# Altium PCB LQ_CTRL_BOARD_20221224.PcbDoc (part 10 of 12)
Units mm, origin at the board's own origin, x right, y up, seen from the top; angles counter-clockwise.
Board outline 260 x 142 mm, 6 copper layers (Top Layer, Mid-Layer 1, Mid-Layer 2, Mid-Layer 3, Mid-Layer 4, Bottom Layer); 1105 components, 1039 nets, 3898 pads, 1277 vias.
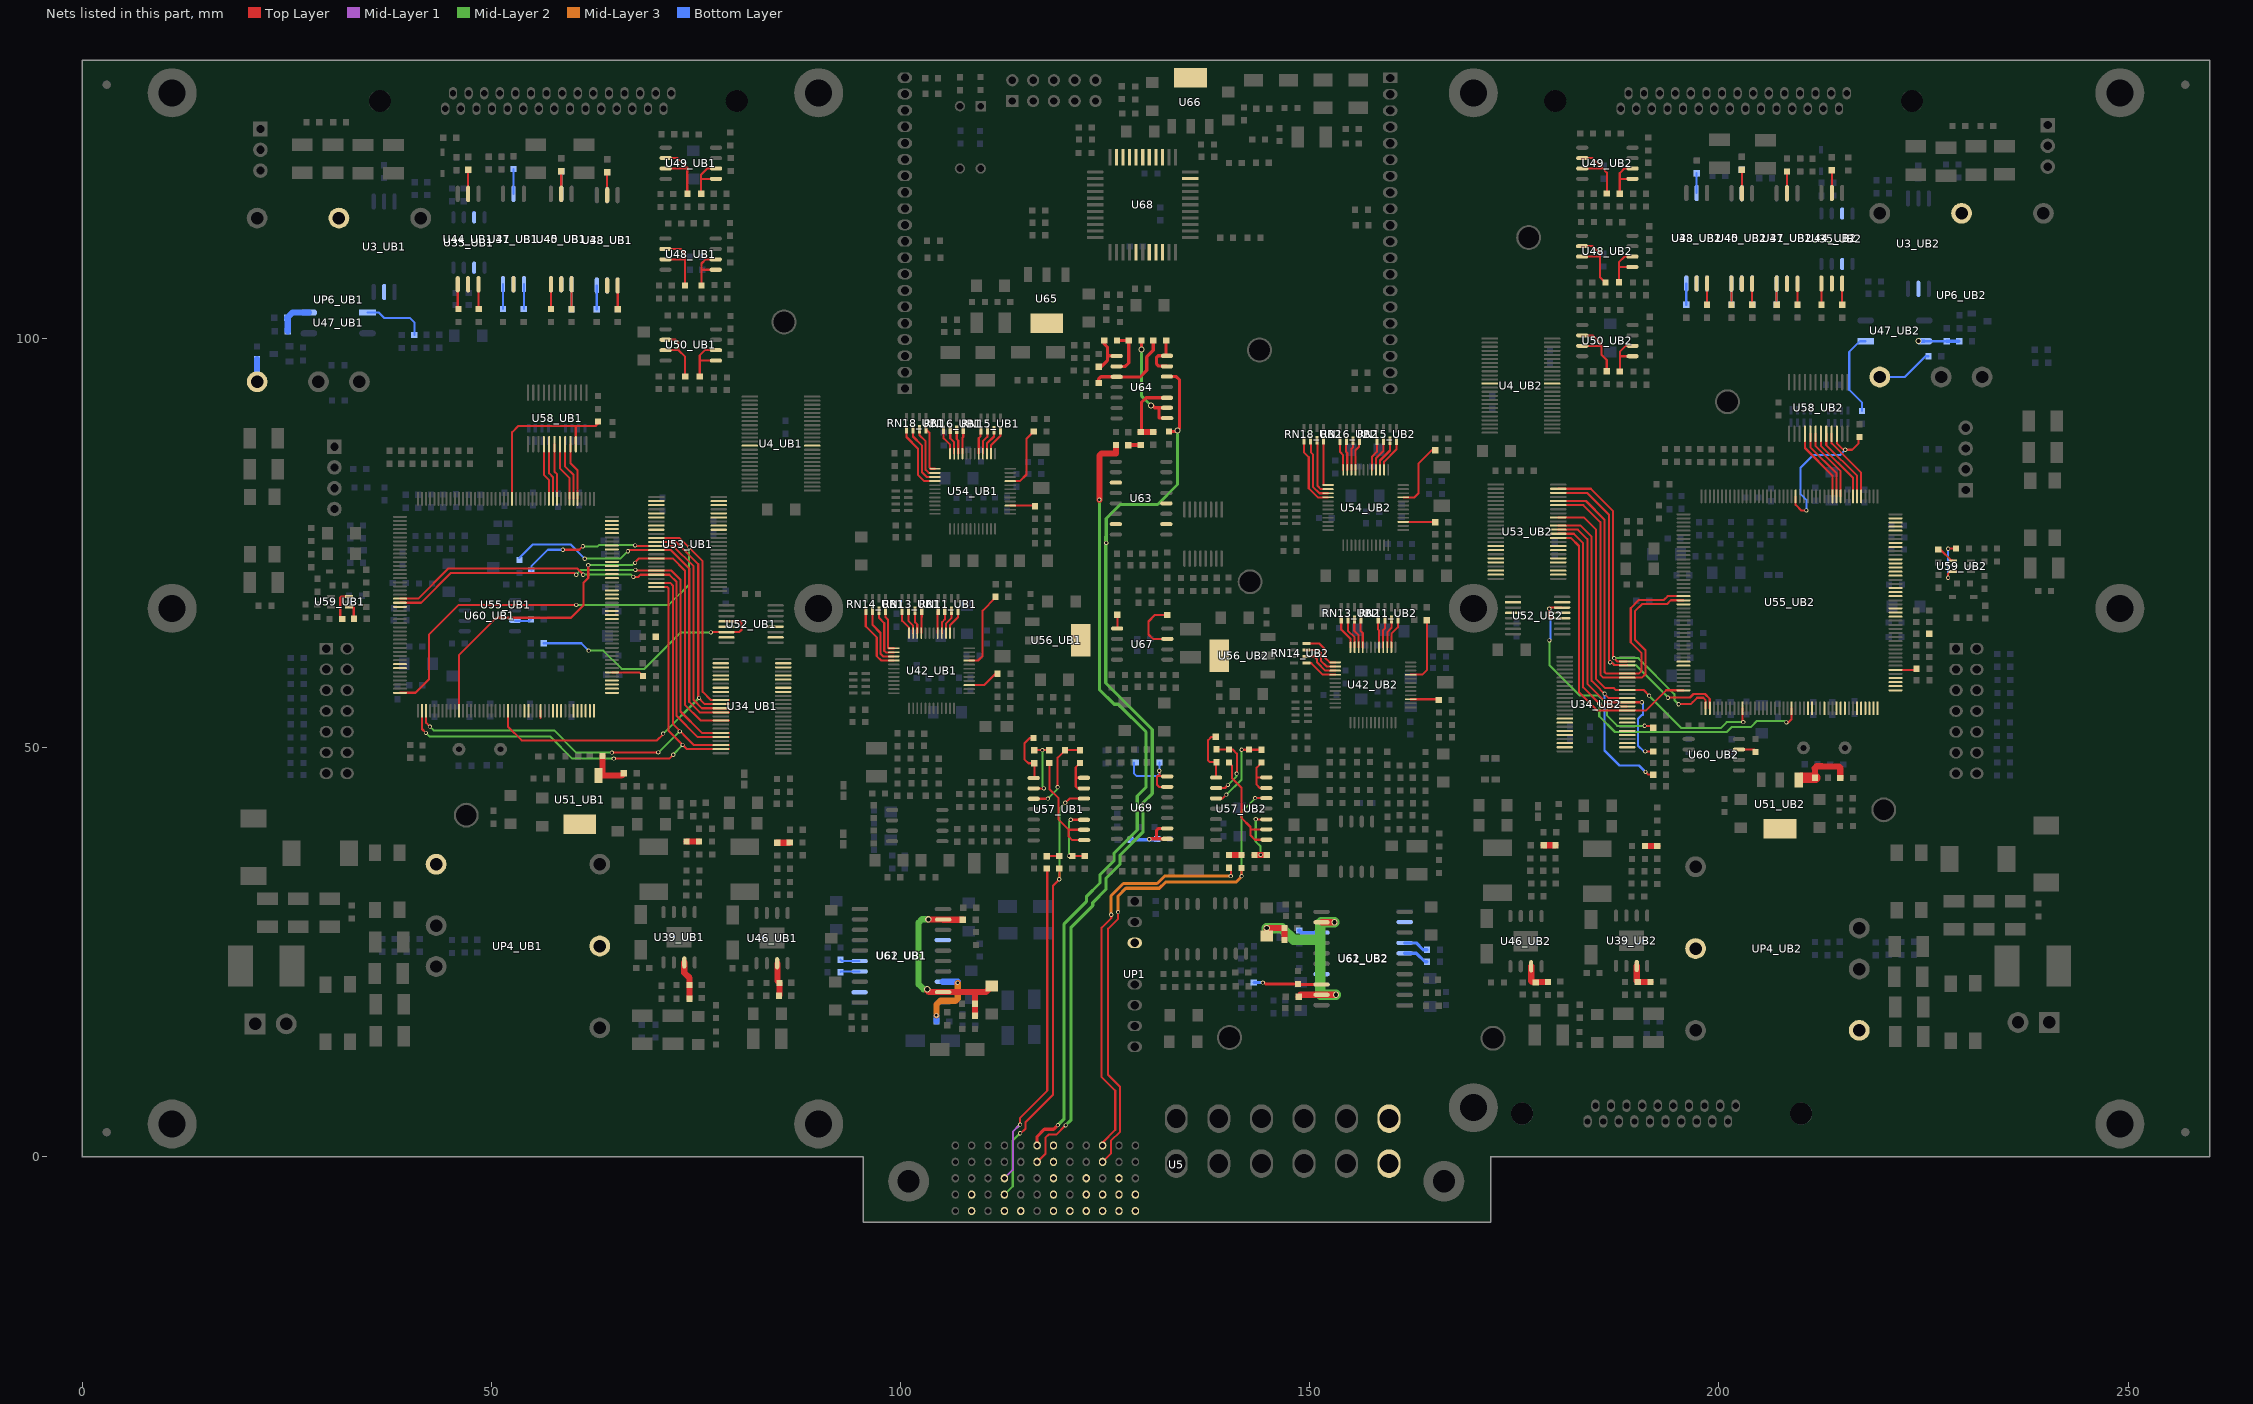
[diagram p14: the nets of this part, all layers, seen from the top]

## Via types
v1: diameter 0.508, hole 0.305, Top Layer to Bottom Layer, 845 vias
v2: diameter 0.762, hole 0.508, Top Layer to Bottom Layer, 317 vias
v3: diameter 1.27, hole 0.762, Top Layer to Bottom Layer, 77 vias
v4: diameter 2.032, hole 1.524, Top Layer to Bottom Layer, 15 vias
v5: diameter 2.032, hole 1.27, Top Layer to Bottom Layer, 11 vias
v6: diameter 1.27, hole 0.711, Top Layer to Bottom Layer, 8 vias
v7: diameter 2.54, hole 1.778, Top Layer to Bottom Layer, 3 vias
v8: diameter 1.524, hole 1.016, Top Layer to Bottom Layer, 1 vias

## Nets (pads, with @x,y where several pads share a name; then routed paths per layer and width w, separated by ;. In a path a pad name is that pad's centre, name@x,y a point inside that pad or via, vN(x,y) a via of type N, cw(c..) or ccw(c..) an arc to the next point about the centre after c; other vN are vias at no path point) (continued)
NetR226_UB2_2: R226_UB2.2 U37_UB2.3 | length 2.6
  Bottom Layer w0.254: U37_UB2.3@207.06,106.68 U37_UB2.3@207.06,106.68 R226_UB2.2@207.061,104.115
NetR227_UB1_2: R227_UB1.2 U38_UB1.3 | length 2.9
  Bottom Layer w0.254: R227_UB1.2@62.89,103.556 U38_UB1.3@62.89,106.451
NetR227_UB2_2: R227_UB2.2 U38_UB2.3 | length 2.6
  Top Layer w0.254: R227_UB2.2@198.552,104.089 198.552,106.7 U38_UB2.3@198.557,106.705
NetR232_UB1_2: R232_UB1.2 U40_UB1.1 | length 3
  Top Layer w0.254: R232_UB1.2@57.282,103.581 U40_UB1.1@57.282,106.604
NetR232_UB2_2: R232_UB2.2 U40_UB2.1 | length 2.6
  Bottom Layer w0.254: R232_UB2.2@204.069,104.089 U40_UB2.1@204.069,106.68
NetR233_UB1_2: R233_UB1.2 U41_UB1.1 | length 3
  Bottom Layer w0.254: R233_UB1.2@53.98,103.581 U41_UB1.1@53.98,106.604
NetR233_UB2_2: R233_UB2.2 U41_UB2.1 | length 2.6
  Top Layer w0.254: U41_UB2.1@207.06,106.68 U41_UB2.1@207.06,106.68 R233_UB2.2@207.061,104.115
NetR235_UB1_1: R235_UB1.1 U41_UB1.5 | length 3
  Bottom Layer w0.254: U41_UB1.5@52.71,117.653 R235_UB1.1@52.71,120.675
NetR235_UB2_1: R235_UB2.1 U41_UB2.5 | length 2.7
  Top Layer w0.254: U41_UB2.5@208.33,117.729 R235_UB2.1@208.33,120.396
NetR236_UB1_2: R236_UB1.2 R243_UB1.1 U39_UB1.3 | length 4.7
  Top Layer w0.762: U39_UB1.3@73.584,23.749 73.584,22.479 74.219,21.844 R236_UB1.2@74.219,20.98 R243_UB1.1@74.219,19.304
NetR236_UB2_2: R236_UB2.2 R243_UB2.1 U39_UB2.3 | length 3.6
  Top Layer w0.762: U39_UB2.3@189.967,23.317 189.967,21.488 R236_UB2.2@190.094,21.361 R243_UB2.1@191.643,21.361
NetR237_UB1_1: R237_UB1.1 U40_UB1.5 | length 2.8
  Top Layer w0.254: U40_UB1.5@58.552,117.653 R237_UB1.1@58.552,120.421
NetR237_UB2_1: R237_UB2.1 U40_UB2.5 | length 2.9
  Bottom Layer w0.254: U40_UB2.5@202.799,117.729 R237_UB2.1@202.799,120.599
NetR238_UB1_2: R238_UB1.2 R239_UB1.1 | length 1.5
  Top Layer w0.762: R239_UB1.1@73.863,38.532 R238_UB1.2@75.387,38.532
NetR238_UB2_2: R238_UB2.2 R239_UB2.1 | length 1.5
  Top Layer w0.762: R239_UB2.1@190.957,37.973 R238_UB2.2@192.456,37.973
NetR240_UB1_2: R240_UB1.2 U40_UB1.3 | length 3.1
  Top Layer w0.254: R240_UB1.2@59.817,103.556 59.817,106.598 U40_UB1.3@59.822,106.604
NetR240_UB2_2: R240_UB2.2 U40_UB2.3 | length 2.6
  Bottom Layer w0.254: R240_UB2.2@201.529,104.089 U40_UB2.3@201.529,106.68
NetR241_UB1_2: R241_UB1.2 U41_UB1.3 | length 3
  Bottom Layer w0.254: R241_UB1.2@51.44,103.581 U41_UB1.3@51.44,106.604
NetR241_UB2_2: R241_UB2.2 U41_UB2.3 | length 2.6
  Top Layer w0.254: U41_UB2.3@209.6,106.68 U41_UB2.3@209.6,106.68 R241_UB2.2@209.601,104.115
NetR244_UB1_2: R244_UB1.2 U42_UB1.3 | length 4
  Top Layer w0.254: U42_UB1.3@108.399,57.635 110.238,57.635 111.608,59.004 R244_UB1.2@111.862,59.004
NetR244_UB2_2: R244_UB2.2 U42_UB2.3 | length 3.5
  Top Layer w0.254: U42_UB2.3@162.334,55.9 R244_UB2.2@165.61,55.9 ; R244_UB2.2@165.61,55.646 R244_UB2.2@165.76,55.796
NetR246_UB1_2: R246_UB1.2 U44_UB1.1 | length 3.1
  Top Layer w0.254: U44_UB1.1@45.904,106.604 45.904,103.656 R246_UB1.2@45.979,103.581
NetR246_UB2_2: R246_UB2.2 U44_UB2.1 | length 2.6
  Top Layer w0.254: R246_UB2.2@212.527,104.089 U44_UB2.1@212.527,106.705
NetR247_UB1_2: R247_UB1.2 U43_UB1.3 | length 2.9
  Top Layer w0.254: U43_UB1.3@65.436,106.451 65.456,106.431 R247_UB1.2@65.456,103.556
NetR247_UB2_2: R247_UB2.2 U43_UB2.3 | length 2.6
  Bottom Layer w0.254: R247_UB2.2@196.012,104.089 196.012,106.7 U43_UB2.3@196.017,106.705
NetR248_UB1_1: R248_UB1.1 U43_UB1.5 | length 2.8
  Top Layer w0.254: U43_UB1.5@64.166,117.5 R248_UB1.1@64.166,120.294
NetR248_UB2_1: R248_UB2.1 U43_UB2.5 | length 2.4
  Bottom Layer w0.254: U43_UB2.5@197.287,117.754 R248_UB2.1@197.287,120.167
NetR249_UB1_2: R249_UB1.2 U45_UB1.1 | length 3.1
  Bottom Layer w0.254: R249_UB1.2@59.817,103.556 59.822,103.561 U45_UB1.1@59.822,106.604
NetR249_UB2_2: R249_UB2.2 U45_UB2.1 | length 2.6
  Top Layer w0.254: R249_UB2.2@201.529,104.089 U45_UB2.1@201.529,106.68
NetR250_UB1_2: R250_UB1.2 UP6_UB1.6 | length 2.7
  Bottom Layer w0.762: R250_UB1.2@21.387,97.434 21.387,94.697 UP6_UB1.6@21.392,94.691
NetR250_UB2_2: R250_UB2.2 UP6_UB2.6 | length 7
  Bottom Layer w0.254: UP6_UB2.6@219.665,95.275 222.707,95.275 225.247,97.815 R250_UB2.2@225.603,97.815
NetR251_UB1_1: R251_UB1.1 U45_UB1.5 | length 2.8
  Bottom Layer w0.254: U45_UB1.5@58.552,117.653 R251_UB1.1@58.552,120.421
NetR251_UB2_1: R251_UB2.1 U45_UB2.5 | length 2.9
  Top Layer w0.254: U45_UB2.5@202.799,117.729 R251_UB2.1@202.799,120.599
NetR252_UB1_1: R252_UB1.1 U44_UB1.5 | length 2.9
  Top Layer w0.254: U44_UB1.5@47.174,117.653 R252_UB1.1@47.174,120.599
NetR252_UB2_1: R252_UB2.1 U44_UB2.5 | length 2.8
  Top Layer w0.254: U44_UB2.5@213.797,117.754 R252_UB2.1@213.797,120.548
NetR253_UB1_2: R253_UB1.2 U44_UB1.3 | length 3
  Top Layer w0.254: U44_UB1.3@48.444,106.604 48.444,103.6 R253_UB1.2@48.463,103.581
NetR253_UB2_2: R253_UB2.2 U44_UB2.3 | length 2.6
  Top Layer w0.254: R253_UB2.2@215.067,104.089 U44_UB2.3@215.067,106.705
NetR254_UB1_2: R254_UB1.2 U45_UB1.3 | length 3
  Bottom Layer w0.254: R254_UB1.2@57.282,103.581 U45_UB1.3@57.282,106.604
NetR254_UB2_2: R254_UB2.2 U45_UB2.3 | length 2.6
  Top Layer w0.254: R254_UB2.2@204.069,104.089 U45_UB2.3@204.069,106.68
NetR255_UB1_2: R255_UB1.2 U42_UB1.9 | length 9.8
  Top Layer w0.254: U42_UB1.9@108.399,60.635 109.479,60.635 110.033,61.189 110.033,66.726 111.597,68.29 R255_UB1.2@111.597,68.428
NetR255_UB2_2: R255_UB2.2 U42_UB2.9 | length 8.3
  Top Layer w0.254: U42_UB2.9@162.334,58.9 163.751,58.9 164.313,59.461 R255_UB2.2@164.313,65.557
NetR256_UB1_1: R256_UB1.1 R260_UB1.2 U47_UB1.6 | length 4.6
  Bottom Layer w0.762: R260_UB1.2@25.121,100.863 25.121,102.464 R256_UB1.1@25.07,102.514 25.705,103.149 U47_UB1.6@27.717,103.149
NetR256_UB2_1: R256_UB2.1 R260_UB2.2 U47_UB2.6 | length 4.8
  Bottom Layer w0.254: U47_UB2.6@225.095,99.644 R260_UB2.2@227.635,99.644
  Bottom Layer w0.381: v2(224.384,99.67) 224.409,99.644 U47_UB2.6@225.095,99.644 ; R260_UB2.2@227.838,99.644 R256_UB2.1@229.362,99.644
NetR257_UB1_1: R257_UB1.1 U47_UB1.1 | length 7.8
  Bottom Layer w0.254: U47_UB1.1@34.88,103.149 36.271,103.149 36.957,102.464 40.081,102.464 40.595,101.95 R257_UB1.1@40.595,100.406
NetR257_UB2_1: R257_UB2.1 U47_UB2.1 | length 10.4
  Bottom Layer w0.254: R257_UB2.1@217.5,91.135 217.5,92.126 215.925,93.701 215.925,98.349 217.221,99.644 U47_UB2.1@217.932,99.644
NetR263_UB1_2: R263_UB1.2 R274_UB1.1 U46_UB1.3 | length 4.1
  Top Layer w0.762: U46_UB1.3@84.988,23.597 84.988,21.463 R263_UB1.2@85.217,21.234 85.217,19.71 R274_UB1.1@85.166,19.66
NetR263_UB2_2: R263_UB2.2 R274_UB2.1 U46_UB2.3 | length 3.9
  Top Layer w0.762: U46_UB2.3@177.063,23.266 177.063,21.488 177.216,21.336 R274_UB2.1@179.121,21.336
NetR265_UB1_1: R265_UB1.1 U48_UB1.6 U48_UB1.7 | length 8.9
  Top Layer w0.254: U48_UB1.7@71.278,109.652 73.665,109.652 ; U48_UB1.6@71.278,110.922 73.127,110.922 73.665,110.383 73.665,109.652 ; R265_UB1.1@73.665,106.451 73.665,109.652
NetR265_UB2_1: R265_UB2.1 U48_UB2.6 U48_UB2.7 | length 8.6
  Top Layer w0.254: U48_UB2.7@183.286,109.987 185.465,109.987 185.471,109.982 ; U48_UB2.6@183.286,111.257 184.551,111.257 185.471,110.338 185.471,109.982 ; R265_UB2.1@186.131,106.807 185.471,107.467 185.471,109.982
NetR266_UB1_1: R266_UB1.1 U49_UB1.1 U49_UB1.2 | length 6.2
  Top Layer w0.254: R266_UB1.1@75.621,117.805 75.621,119.482 ; U49_UB1.1@77.462,119.482 75.621,119.482 ; U49_UB1.2@77.462,120.752 76.403,120.752 75.621,119.97 75.621,119.482
NetR266_UB2_1: R266_UB2.1 U49_UB2.1 U49_UB2.2 | length 5.9
  Top Layer w0.254: R266_UB2.1@187.884,117.678 187.884,120.177 188.458,120.752 U49_UB2.2@189.459,120.752 ; 187.909,119.405 187.985,119.482 U49_UB2.1@189.459,119.482
NetR267_UB1_1: R267_UB1.1 U50_UB1.6 U50_UB1.7 | length 7.8
  Top Layer w0.254: U50_UB1.7@71.303,98.552 72.873,98.552 ; U50_UB1.6@71.303,99.822 72.517,99.822 72.873,99.466 72.873,98.552 ; R267_UB1.1@73.691,95.326 73.691,97.734 72.873,98.552
NetR267_UB2_1: R267_UB2.1 U50_UB2.6 U50_UB2.7 | length 8.6
  Top Layer w0.254: U50_UB2.7@183.312,99.085 185.598,99.085 ; U50_UB2.6@183.312,100.355 184.582,100.355 185.661,99.276 185.661,97.98 186.296,97.346 R267_UB2.1@186.296,95.987
NetR268_UB1_2: R268_UB1.2 R269_UB1.1 | length 1.5
  Top Layer w0.762: R269_UB1.1@84.938,38.379 86.436,38.379 R268_UB1.2@86.462,38.405
NetR268_UB2_2: R268_UB2.2 R269_UB2.1 | length 1.4
  Top Layer w0.762: R269_UB2.1@178.587,38.049 R268_UB2.2@180.035,38.049
NetR282_UB1_1: R282_UB1.1 U48_UB1.1 U48_UB1.2 | length 6.4
  Top Layer w0.254: R282_UB1.1@75.692,106.451 75.692,108.473 ; U48_UB1.1@77.425,108.382 75.783,108.382 75.692,108.473 ; U48_UB1.2@77.425,109.652 76.2,109.652 75.692,109.144 75.692,108.473
NetR282_UB2_1: R282_UB2.1 U48_UB2.1 U48_UB2.2 | length 6
  Top Layer w0.254: R282_UB2.1@187.782,106.858 187.782,108.737 ; U48_UB2.1@189.433,108.717 187.802,108.717 187.782,108.737 ; U48_UB2.2@189.433,109.987 188.464,109.987 187.782,109.306 187.782,108.737
NetR285_UB1_1: R285_UB1.1 U49_UB1.6 U49_UB1.7 | length 8.8
  Top Layer w0.254: U49_UB1.7@71.315,120.752 73.869,120.752 73.945,120.675 ; U49_UB1.6@71.315,122.022 72.771,122.022 73.945,120.848 73.945,120.675 ; R285_UB1.1@73.945,117.805 73.945,120.675
NetR285_UB2_1: R285_UB2.1 U49_UB2.6 U49_UB2.7 | length 8.8
  Top Layer w0.254: U49_UB2.7@183.312,120.752 185.776,120.752 185.788,120.764 ; U49_UB2.6@183.312,122.022 184.531,122.022 185.788,120.764 ; R285_UB2.1@186.309,117.704 186.309,120.244 185.788,120.764
NetR286_UB1_1: R286_UB1.1 U50_UB1.1 U50_UB1.2 | length 6.9
  Top Layer w0.254: R286_UB1.1@75.469,95.326 75.469,97.13 ; U50_UB1.1@77.45,97.282 75.621,97.282 75.469,97.13 ; U50_UB1.2@77.45,98.552 76.104,98.552 75.469,97.917 75.469,97.13
NetR286_UB2_1: R286_UB2.1 U50_UB2.1 U50_UB2.2 | length 5.9
  Top Layer w0.254: R286_UB2.1@187.896,95.936 187.896,97.815 ; U50_UB2.1@189.459,97.815 187.896,97.815 ; U50_UB2.2@189.459,99.085 188.62,99.085 187.896,98.361 187.896,97.815
NetR294_UB1_2: R294_UB1.2 R295_UB1.1 U51_UB1.1 | length 5.8
  Top Layer w0.762: R295_UB1.1@63.602,48.971 63.602,47.092 U51_UB1.1@63.094,46.584 65.913,46.584 R294_UB1.2@66.192,46.863
NetR294_UB2_2: R294_UB2.2 R295_UB2.1 U51_UB2.1 | length 7.5
  Top Layer w0.762: R295_UB2.1@211.76,46.304 211.76,47.422 211.709,47.473 211.938,47.701 212.573,47.701 212.598,47.676 214.681,47.676 214.833,47.523 R294_UB2.2@214.833,46.279
  Top Layer w1.27: U51_UB2.1@210.033,46.304 R295_UB2.1@211.76,46.304
NetR308_UB1_2: R308_UB1.2 U54_UB1.3 | length 3.1
  Top Layer w0.254: U54_UB1.3@113.413,79.56 116.35,79.56 R308_UB1.2@116.434,79.477
NetR308_UB2_2: R308_UB2.2 U54_UB2.3 | length 3.9
  Top Layer w0.254: U54_UB2.3@161.442,77.573 165.301,77.573 R308_UB2.2@165.354,77.52
NetR310_UB1_2: R310_UB1.2 U54_UB1.9 | length 7.9
  Top Layer w0.254: U54_UB1.9@113.413,82.56 114.59,82.56 115.392,83.363 115.392,87.732 R310_UB1.2@116.281,88.621
NetR310_UB2_2: R310_UB2.2 U54_UB2.9 | length 8.4
  Top Layer w0.254: U54_UB2.9@161.442,80.573 162.805,80.573 163.271,81.039 163.271,84.684 164.924,86.336 R310_UB2.2@165.343,86.336
NetR332_UB1_1: R332_UB1.1 R338_UB1.1 U57_UB1.1 | length 6.6
  Top Layer w0.254: R338_UB1.1@116.25,51.181 115.824,51.181 115.138,50.495 115.138,48.59 115.646,48.082 R332_UB1.1@116.357,48.082 116.357,46.36 U57_UB1.1@116.276,46.279
NetR332_UB1_2: R332_UB1.2 R333_UB1.1 U57_UB1.2 | length 7.8
  Top Layer w0.254: U57_UB1.2@116.276,45.009 v1(117.526,45.009) ; R332_UB1.2@116.357,49.657 116.383,49.682 v1(117.348,49.682) R333_UB1.1@118.186,49.682
  Mid-Layer 2 w0.254: v1(117.348,49.682) 117.348,45.187 v1(117.526,45.009)
NetR332_UB2_1: R332_UB2.1 R338_UB2.1 U57_UB2.1 | length 6.6
  Top Layer w0.254: R338_UB2.1@138.532,51.308 137.998,51.308 137.592,50.902 137.592,48.412 137.795,48.209 R332_UB2.1@138.608,48.209 138.557,48.158 U57_UB2.1@138.557,46.33
NetR332_UB2_2: R332_UB2.2 R333_UB2.1 U57_UB2.2 | length 8.6
  Top Layer w0.254: U57_UB2.2@138.557,45.06 139.649,45.06 140.005,45.415 v1(140.005,45.441) ; R332_UB2.2@138.608,49.784 140.106,49.784 R333_UB2.1@140.132,49.759 140.601,49.759 141.097,49.262 141.097,46.838 v1(141.072,46.812)
  Mid-Layer 2 w0.254: v1(140.005,45.441) 140.03,45.441 141.072,46.482 v1(141.072,46.812)
NetR333_UB1_2: R333_UB1.2 U57_UB1.8 U57_UB1.9 | length 13.9
  Top Layer w0.254: R333_UB1.2@118.186,48.108 118.186,44.933 119.316,43.803 119.316,41.187 120.548,39.954 ; U57_UB1.9@122.423,39.954 120.548,39.954 ; U57_UB1.8@122.448,38.684 121.006,38.684 120.548,39.141 120.548,39.954
NetR333_UB2_2: R333_UB2.2 U57_UB2.8 U57_UB2.9 | length 14.1
  Top Layer w0.254: R333_UB2.2@140.132,48.184 140.487,47.828 140.487,46.279 141.656,45.11 141.656,41.402 142.773,40.284 142.773,40.011 ; U57_UB2.9@144.704,40.005 142.779,40.005 142.773,40.011 ; U57_UB2.8@144.729,38.735 143.307,38.735 142.773,39.268 142.773,40.011
NetR334_UB1_2: R334_UB1.2 R340_UB1.1 U57_UB1.10 | length 8.1
  Top Layer w0.254: v1(120.574,36.754) R340_UB1.1@120.98,36.754 R334_UB1.2@122.504,36.754 ; v1(120.802,41.173) U57_UB1.10@122.423,41.173
  Mid-Layer 2 w0.254: v1(120.574,36.754) 120.574,40.945 v1(120.802,41.173)
NetR334_UB2_2: R334_UB2.2 R340_UB2.1 U57_UB2.10 | length 7.4
  Top Layer w0.254: v1@143.434,41.224 U57_UB2.10@144.704,41.224
  Top Layer w0.762: R340_UB2.1@143.256,36.881 v1(144.005,36.881) R334_UB2.2@144.755,36.881
  Mid-Layer 2 w0.254: v1(143.408,41.25) 143.408,38.506 144.005,37.91 v1(144.005,36.881)
NetR339_UB1_1: R339_UB1.1 R344_UB1.1 U57_UB1.3 | length 10.4
  Top Layer w0.254: U57_UB1.3@116.276,43.739 117.983,43.739 v1(118.008,43.764) ; v1(119.202,45.161) 119.202,48.768 R344_UB1.1@120.117,49.682 R339_UB1.1@121.945,49.682
  Mid-Layer 2 w0.254: v1(118.008,43.764) 119.202,44.958 v1(119.202,45.161)
NetR339_UB1_2: R339_UB1.2 U57_UB1.13 U57_UB1.14 | length 5.2
  Top Layer w0.254: R339_UB1.2@121.945,48.108 121.412,47.574 121.412,46.228 ; U57_UB1.13@122.423,45.009 121.641,45.009 121.412,45.237 121.412,46.228 ; U57_UB1.14@122.423,46.304 121.488,46.304 121.412,46.228
NetR339_UB2_1: R339_UB2.1 R344_UB2.1 U57_UB2.3 | length 10.4
  Top Layer w0.254: U57_UB2.3@138.557,43.79 139.37,43.79 v1(139.827,44.247) ; v1(141.681,49.733) R339_UB2.1@144.12,49.733
  Mid-Layer 2 w0.254: v1(139.827,44.247) 141.681,46.101 ; v1@141.567,49.619 141.681,49.505 141.681,46.101 ; 141.681,46.406 141.681,46.101
NetR339_UB2_2: R339_UB2.2 U57_UB2.13 U57_UB2.14 | length 5.5
  Top Layer w0.254: R339_UB2.2@144.12,48.158 143.51,47.549 143.51,46.33 ; U57_UB2.13@144.704,45.06 143.916,45.06 143.51,45.466 143.51,46.33 ; U57_UB2.14@144.704,46.355 143.535,46.355 143.51,46.33
NetR340_UB1_2: R340_UB1.2 R342_UB1.2 | length 1.5
  Top Layer w0.254: R342_UB1.2@117.881,36.728 117.907,36.754 R340_UB1.2@119.405,36.754
NetR340_UB2_2: R340_UB2.2 R342_UB2.2 | length 1.5
  Top Layer w0.762: R342_UB2.2@140.157,36.855 141.656,36.855 R340_UB2.2@141.681,36.881
NetR345_UB1_1: R345_UB1.1 U55_UB1.138 | length 4
  Top Layer w0.254: U55_UB1.138@64.74,59.191 68.088,59.191 R345_UB1.1@68.555,58.725
NetR345_UB2_1: R345_UB2.1 U55_UB2.138 | length 2.6
  Top Layer w0.254: U55_UB2.138@221.585,59.496 224.012,59.496 R345_UB2.1@224.155,59.639
NetR355_UB1_2: R355_UB1.2 U59_UB1.4 | length 2.3
  Top Layer w0.254: U59_UB1.4@32.62,67.153 33.126,67.153 33.198,67.081 33.198,65.786 R355_UB1.2@33.474,65.51
NetR355_UB2_2: R355_UB2.2 U59_UB2.4 | length 2.4
  Top Layer w0.254: R355_UB2.2@226.797,74.188 227.081,74.188 228.443,72.826 U59_UB2.4@228.595,72.826
NetR356_UB1_1: R356_UB1.1 U59_UB1.6 | length 3.8
  Top Layer w0.254: R356_UB1.1@31.699,65.659 31.547,65.811 31.547,68.301 31.699,68.453 U59_UB1.6@32.62,68.453
NetR356_UB2_1: R356_UB2.1 U59_UB2.6 | length 5.7
  Top Layer w0.254: v1(228.016,70.739) 228.016,71.272 228.219,71.476 228.544,71.476 U59_UB2.6@228.595,71.526 ; v1(228.016,74.295) 228.956,74.295 R356_UB2.1@228.981,74.32
  Bottom Layer w0.254: v1(228.016,70.739) v1(228.016,74.295)
NetR358_UB1_1: R358_UB1.1 U60_UB1.7 | length 2
  Bottom Layer w0.254: U60_UB1.7@52.908,65.481 54.661,65.481 R358_UB1.1@54.839,65.659
NetR358_UB2_1: R358_UB2.1 U60_UB2.7 | length 2.1
  Top Layer w0.254: U60_UB2.7@202.459,49.759 204.292,49.759 R358_UB2.1@204.47,49.581
NetR367_UB1_2: R367_UB1.2 U61_UB1.18 | length 8.7
  Mid-Layer 3 w0.762: v1(104.394,17.272) 104.394,18.567 104.877,19.05 106.731,19.05 106.985,19.304 v1(106.985,21.234)
  Bottom Layer w0.762: R367_UB1.2@104.394,16.535 v1(104.394,17.272) ; U61_UB1.18@105.161,21.387 v1@106.985,21.387
NetR367_UB2_2: R367_UB2.2 U61_UB2.18 | length 2.9
  Bottom Layer w0.508: R367_UB2.2@148.717,27.635 149.047,27.305 151.373,27.305 U61_UB2.18@151.449,27.381
NetR368_UB1_1: R368_UB1.1 U61_UB1.4 | length 2.4
  Bottom Layer w0.254: R368_UB1.1@92.659,22.555 92.735,22.631 U61_UB1.4@95.001,22.631
NetR368_UB2_1: R368_UB2.1 U61_UB2.4 | length 3.1
  Bottom Layer w0.381: U61_UB2.4@161.609,26.137 163.017,26.137 163.855,25.298 R368_UB2.1@164.338,25.298
NetR369_UB1_1: R369_UB1.1 U61_UB1.5 | length 2.4
  Bottom Layer w0.254: R369_UB1.1@92.659,24.079 92.837,23.901 U61_UB1.5@95.001,23.901
NetR369_UB2_1: R369_UB2.1 U61_UB2.5 | length 3.2
  Bottom Layer w0.381: U61_UB2.5@161.609,24.867 163.043,24.867 164.084,23.825 R369_UB2.1@164.338,23.825
NetR372_1: R372.1 R379.1 U64.1 | length 5.1
  Top Layer w0.381: R379.1@124.231,96.52 124.536,96.52 125.285,97.269 125.285,98.946 124.892,99.339 R372.1@124.892,99.72 ; 125.374,97.866 U64.1@125.908,97.866 ; U64.1@125.857,97.841 U64.1@126.416,97.841
NetR372_2: R372.2 R373.1 U64.2 | length 5.8
  Top Layer w0.381: U64.2@126.416,96.571 127.483,96.571 127.889,96.977 R373.1@127.889,99.746 127.864,99.72 R372.2@126.467,99.72
NetR373_2: R373.2 U64.8 U64.9 | length 13.6
  Top Layer w0.381: v2(129.464,98.628) R373.2@129.464,99.746 ; v2@130.683,91.897 131.064,91.516 U64.9@132.563,91.516 132.521,91.474 131.699,91.474 131.572,91.347 131.572,90.348 131.674,90.246 U64.8@132.588,90.246
  Mid-Layer 2 w0.381: v2(129.464,98.628) 129.464,92.939 v2(130.607,91.796)
NetR375_2: R375.2 R381.1 U64.10 | length 8.6
  Top Layer w0.381: R381.1@129.438,88.494 129.438,92.151 130.023,92.735 U64.10@132.563,92.735 ; R375.2@130.861,88.595 R375.2@130.886,88.57
  Top Layer w0.762: R381.1@129.362,88.544 130.861,88.544 R375.2@130.886,88.57
NetR380_1: R380.1 R385.1 U64.3 | length 10.8
  Top Layer w0.381: R385.1@124.231,94.539 124.231,95.047 124.485,95.301 U64.3@126.416,95.301 126.441,95.275 129.286,95.275 130.099,96.088 130.099,97.739 130.886,98.527 R380.1@130.886,99.746
NetR380_2: R380.2 U64.13 U64.14 | length 5.5
  Top Layer w0.381: R380.2@132.461,99.746 132.461,97.968 U64.14@132.563,97.866 131.47,97.866 131.293,97.688 131.293,96.85 131.547,96.596 132.537,96.596 U64.13@132.563,96.571
NetR381_2: R381.2 R383.2 | length 1.5
  Top Layer w0.508: R383.2@127.838,86.944 127.864,86.97 R381.2@129.362,86.97
NetR397_2: R397.2 U67.3 | length 6.7
  Top Layer w0.254: R397.2@132.588,66.192 131.089,66.192 130.302,65.405 130.302,63.805 130.835,63.271 U67.3@132.608,63.271
NetR408_2: R408.2 U67.5 | length 1.7
  Top Layer w0.254: U67.5@126.461,64.541 126.492,64.572 R408.2@126.492,66.218
NetR409_1: R409.1 R410.1 U69.1 U69.2 | length 7.9
  Top Layer w0.381: v1@130.404,38.837 130.416,38.849 131.293,38.849 ; U69.1@132.593,38.849 131.293,38.849 ; U69.2@132.593,40.119 131.508,40.119 131.293,39.903 131.293,38.849
  Bottom Layer w0.381: R409.1@128.118,38.735 131.267,38.735 R410.1@131.369,38.837
  other v1: 130.404,38.786
NetR419_1: R419.1 R420.1 U69.6 U69.7 | length 10.4
  Top Layer w0.254: v1(131.623,47.168) 131.674,47.117 131.674,46.507 ; U69.6@132.593,45.199 131.585,45.199 131.343,45.441 131.343,46.507 131.674,46.507 ; U69.7@132.593,46.469 132.555,46.507 131.674,46.507
  Bottom Layer w0.254: R419.1@128.524,48.158 128.524,46.838 128.854,46.507 131.343,46.507 131.648,46.812 R420.1@131.648,48.184
NetRN11_UB1_2: RN11_UB1.2 U42_UB1.14 | length 3.1
  Top Layer w0.254: U42_UB1.14@106.049,63.985 106.049,64.926 107.017,65.894 RN11_UB1.2@107.017,66.726
NetRN11_UB1_4: RN11_UB1.4 U42_UB1.15 | length 3
  Top Layer w0.254: U42_UB1.15@105.549,63.985 105.549,65.137 106.216,65.805 RN11_UB1.4@106.216,66.726
NetRN11_UB1_6: RN11_UB1.6 U42_UB1.16 | length 2.9
  Top Layer w0.254: U42_UB1.16@105.049,63.985 105.049,65.245 105.091,65.287 105.091,65.327 105.416,65.652 RN11_UB1.6@105.416,66.726
NetRN11_UB1_8: RN11_UB1.8 U42_UB1.17 | length 2.8
  Top Layer w0.254: U42_UB1.17@104.549,63.985 104.549,65.098 104.549,66.658 RN11_UB1.8@104.616,66.726
NetRN11_UB2_2: RN11_UB2.2 U42_UB2.14 | length 3.7
  Top Layer w0.254: U42_UB2.14@159.984,62.25 159.984,63.889 160.781,64.686 RN11_UB2.2@160.781,65.634
NetRN11_UB2_4: RN11_UB2.4 U42_UB2.15 | length 3.6
  Top Layer w0.254: U42_UB2.15@159.484,62.25 159.484,64.107 159.98,64.603 RN11_UB2.4@159.98,65.634
NetRN11_UB2_6: RN11_UB2.6 U42_UB2.16 | length 3.5
  Top Layer w0.254: U42_UB2.16@158.984,62.25 158.984,64.343 159.18,64.54 RN11_UB2.6@159.18,65.634
NetRN11_UB2_8: RN11_UB2.8 U42_UB2.17 | length 3.4
  Top Layer w0.254: RN11_UB2.8@158.38,65.634 158.369,65.622 158.369,64.414 158.484,64.3 U42_UB2.17@158.484,62.25
NetRN13_UB1_2: RN13_UB1.2 U42_UB1.21 | length 3.3
  Top Layer w0.254: U42_UB1.21@102.549,63.985 RN13_UB1.2@102.549,66.65 ; 102.597,65.981 RN13_UB1.2@102.597,66.65
NetRN13_UB1_4: RN13_UB1.4 U42_UB1.22 | length 2.8
  Top Layer w0.254: RN13_UB1.4@101.797,66.65 101.797,66.134 101.797,65.296 102.049,65.044 U42_UB1.22@102.049,63.985
NetRN13_UB1_6: RN13_UB1.6 U42_UB1.23 | length 3
  Top Layer w0.254: RN13_UB1.6@100.997,66.726 100.997,65.449 101.549,64.898 U42_UB1.23@101.549,63.985
NetRN13_UB1_8: RN13_UB1.8 U42_UB1.24 | length 3.1
  Top Layer w0.254: RN13_UB1.8@100.203,66.726 100.203,65.481 101.049,64.636 U42_UB1.24@101.049,63.985
NetRN13_UB2_2: RN13_UB2.2 U42_UB2.21 | length 3.5
  Top Layer w0.254: RN13_UB2.2@156.259,65.634 156.21,65.584 156.21,64.262 156.484,63.988 U42_UB2.21@156.484,62.25
NetRN13_UB2_4: RN13_UB2.4 U42_UB2.22 | length 3.6
  Top Layer w0.254: RN13_UB2.4@155.459,65.634 155.448,65.622 155.448,64.237 155.984,63.701 U42_UB2.22@155.984,62.25
NetRN13_UB2_6: RN13_UB2.6 U42_UB2.23 | length 3.7
  Top Layer w0.254: RN13_UB2.6@154.659,65.634 154.659,64.29 155.484,63.466 U42_UB2.23@155.484,62.25
NetRN13_UB2_8: RN13_UB2.8 U42_UB2.24 | length 3.8
  Top Layer w0.254: RN13_UB2.8@153.859,65.634 153.859,64.429 154.984,63.304 U42_UB2.24@154.984,62.25
NetRN14_UB1_2: RN14_UB1.2 U42_UB1.25 | length 5.2
  Top Layer w0.254: RN14_UB1.2@98.177,66.573 98.177,65.907 98.476,65.608 98.476,62.205 98.546,62.135 U42_UB1.25@99.199,62.135
NetRN14_UB1_4: RN14_UB1.4 U42_UB1.26 | length 6.3
  Top Layer w0.254: RN14_UB1.4@97.377,66.573 97.377,65.843 98.019,65.202 98.019,61.824 98.207,61.635 U42_UB1.26@99.199,61.635
NetRN14_UB1_6: RN14_UB1.6 U42_UB1.27 | length 7.3
  Top Layer w0.254: RN14_UB1.6@96.577,66.573 96.577,65.82 96.577,64.981 97.561,63.997 97.561,61.443 97.869,61.135 U42_UB1.27@99.199,61.135
NetRN14_UB1_8: RN14_UB1.8 U42_UB1.28 | length 8.5
  Top Layer w0.254: RN14_UB1.8@95.758,66.777 95.758,64.81 97.104,63.464 97.104,61.174 97.643,60.635 U42_UB1.28@99.199,60.635
NetRN14_UB2_2: RN14_UB2.2 U42_UB2.25 | length 5.1
  Top Layer w0.254: RN14_UB2.2@149.606,62.719 151.174,62.719 151.867,62.027 151.867,60.985 152.452,60.4 U42_UB2.25@153.134,60.4
NetRN14_UB2_4: RN14_UB2.4 U42_UB2.26 | length 5
  Top Layer w0.254: RN14_UB2.4@149.606,61.919 151.06,61.919 151.359,61.62 151.359,60.604 152.063,59.9 U42_UB2.26@153.134,59.9
NetRN14_UB2_6: RN14_UB2.6 U42_UB2.27 | length 4.5
  Top Layer w0.254: RN14_UB2.6@149.606,61.119 150.59,61.119 150.901,60.808 150.901,60.415 151.917,59.4 U42_UB2.27@153.134,59.4
NetRN14_UB2_8: RN14_UB2.8 U42_UB2.28 | length 4.1
  Top Layer w0.254: RN14_UB2.8@149.606,60.319 150.197,60.319 151.615,58.9 U42_UB2.28@153.134,58.9
NetRN15_UB1_2: RN15_UB1.2 U54_UB1.14 | length 3.3
  Top Layer w0.254: U54_UB1.14@111.063,85.91 111.063,86.933 112.224,88.094 RN15_UB1.2@112.224,88.773
NetRN15_UB1_4: RN15_UB1.4 U54_UB1.15 | length 3.2
  Top Layer w0.254: U54_UB1.15@110.563,85.91 110.563,87.144 111.423,88.005 RN15_UB1.4@111.423,88.773
NetRN15_UB1_6: RN15_UB1.6 U54_UB1.16 | length 3.1
  Top Layer w0.254: U54_UB1.16@110.063,85.91 110.063,87.406 110.623,87.967 RN15_UB1.6@110.623,88.773
NetRN15_UB1_8: RN15_UB1.8 U54_UB1.17 | length 3
  Top Layer w0.254: U54_UB1.17@109.563,85.91 109.563,87.795 109.753,87.986 109.753,88.703 RN15_UB1.8@109.823,88.773
NetRN15_UB2_2: RN15_UB2.2 U54_UB2.14 | length 4.2
  Top Layer w0.254: U54_UB2.14@159.092,83.923 159.092,84.924 160.611,86.442 RN15_UB2.2@160.611,87.503
NetRN15_UB2_4: RN15_UB2.4 U54_UB2.15 | length 4.1
  Top Layer w0.254: U54_UB2.15@158.592,83.923 158.592,85.07 159.81,86.289 RN15_UB2.4@159.81,87.503
NetRN15_UB2_6: RN15_UB2.6 U54_UB2.16 | length 4
  Top Layer w0.254: U54_UB2.16@158.092,83.923 158.092,85.321 159.01,86.239 RN15_UB2.6@159.01,87.503
NetRN15_UB2_8: RN15_UB2.8 U54_UB2.17 | length 3.8
  Top Layer w0.254: U54_UB2.17@157.592,83.923 157.592,85.507 158.21,86.125 RN15_UB2.8@158.21,87.503
NetRN16_UB1_2: RN16_UB1.2 U54_UB1.21 | length 3
  Top Layer w0.254: U54_UB1.21@107.563,85.91 107.563,87.827 107.671,87.935 107.671,88.817 RN16_UB1.2@107.677,88.824
NetRN16_UB1_4: RN16_UB1.4 U54_UB1.22 | length 3
  Top Layer w0.254: RN16_UB1.4@106.877,88.824 106.877,87.687 107.063,87.501 U54_UB1.22@107.063,85.91
NetRN16_UB1_6: RN16_UB1.6 U54_UB1.23 | length 3.1
  Top Layer w0.254: RN16_UB1.6@106.077,88.824 106.077,87.776 106.563,87.29 U54_UB1.23@106.563,85.91
NetRN16_UB1_8: RN16_UB1.8 U54_UB1.24 | length 3.2
  Top Layer w0.254: RN16_UB1.8@105.277,88.824 105.277,87.789 106.063,87.002 U54_UB1.24@106.063,85.91
NetRN16_UB2_2: RN16_UB2.2 U54_UB2.21 | length 3.8
  Top Layer w0.254: U54_UB2.21@155.592,83.923 155.592,86.326 156.032,86.766 156.032,87.431 RN16_UB2.2@156.104,87.503
NetRN16_UB2_4: RN16_UB2.4 U54_UB2.22 | length 3.7
  Top Layer w0.254: U54_UB2.22@155.092,83.923 155.092,86.473 155.304,86.684 RN16_UB2.4@155.304,87.503
NetRN16_UB2_6: RN16_UB2.6 U54_UB2.23 | length 3.7
  Top Layer w0.254: RN16_UB2.6@154.504,87.503 154.457,87.456 154.457,86.131 154.592,85.996 U54_UB2.23@154.592,83.923
NetRN16_UB2_8: RN16_UB2.8 U54_UB2.24 | length 3.7
  Top Layer w0.254: RN16_UB2.8@153.704,87.503 153.704,86.123 154.092,85.734 U54_UB2.24@154.092,83.923
NetRN18_UB1_2: RN18_UB1.2 U54_UB1.25 | length 5.5
  Top Layer w0.254: RN18_UB1.2@103.13,88.875 103.53,88.475 103.53,84.277 103.747,84.06 U54_UB1.25@104.213,84.06
NetRN18_UB1_4: RN18_UB1.4 U54_UB1.26 | length 6.5
  Top Layer w0.254: RN18_UB1.4@102.33,88.875 102.33,88.144 103.073,87.401 103.073,83.928 103.441,83.56 U54_UB1.26@104.213,83.56
NetRN18_UB1_6: RN18_UB1.6 U54_UB1.27 | length 7.5
  Top Layer w0.254: RN18_UB1.6@101.53,88.875 101.53,88.005 102.616,86.919 102.616,83.662 103.218,83.06 U54_UB1.27@104.213,83.06
NetRN18_UB1_8: RN18_UB1.8 U54_UB1.28 | length 8.5
  Top Layer w0.254: RN18_UB1.8@100.73,88.875 100.73,87.941 102.133,86.538 102.133,83.325 102.898,82.56 U54_UB1.28@104.213,82.56
NetRN18_UB2_2: RN18_UB2.2 U54_UB2.25 | length 6
  Top Layer w0.254: RN18_UB2.2@151.695,87.528 151.714,87.509 151.714,82.118 151.759,82.073 U54_UB2.25@152.242,82.073
NetRN18_UB2_4: RN18_UB2.4 U54_UB2.26 | length 7
  Top Layer w0.254: RN18_UB2.4@150.895,87.528 150.952,87.471 150.952,81.965 151.344,81.573 U54_UB2.26@152.242,81.573
NetRN18_UB2_6: RN18_UB2.6 U54_UB2.27 | length 8
  Top Layer w0.254: RN18_UB2.6@150.095,87.528 150.139,87.484 150.139,86.08 150.393,85.826 150.393,81.878 151.198,81.073 U54_UB2.27@152.242,81.073
NetRN18_UB2_8: RN18_UB2.8 U54_UB2.28 | length 8.9
  Top Layer w0.254: RN18_UB2.8@149.295,87.528 149.295,86.061 149.885,85.471 149.885,81.686 150.998,80.573 U54_UB2.28@152.242,80.573
NetU3_UB1_2: U3_UB1.2
NetU3_UB2_2: U3_UB2.2
NetU4_UB1_12: U4_UB1.12
NetU4_UB1_37: U4_UB1.37
NetU4_UB2_12: U4_UB2.12
NetU4_UB2_37: U4_UB2.37
NetU5_6: U5.6
NetU5_12: U5.12
NetU5_A2: U5.A2
NetU5_A4: U5.A4
NetU5_A5: U5.A5
NetU5_A7: U5.A7
NetU5_A8: U5.A8
NetU5_A9: U5.A9
NetU5_A10: U5.A10
NetU5_A11: U5.A11
NetU5_A12: U5.A12
NetU5_B2: U5.B2
NetU5_B7: U5.B7
NetU5_B9: U5.B9
NetU5_B10: U5.B10
NetU5_B11: U5.B11
NetU5_B12: U5.B12
NetU5_C7: U5.C7
NetU5_C9: U5.C9
NetU5_C11: U5.C11
NetU5_D7: U5.D7
NetU5_E7: U5.E7
NetU34_UB1_16: U34_UB1.16
NetU34_UB1_17: U34_UB1.17
NetU34_UB1_19: U34_UB1.19
NetU34_UB1_20: U34_UB1.20
NetU34_UB1_22: U34_UB1.22
NetU34_UB1_23: U34_UB1.23
NetU34_UB1_26: U34_UB1.26
NetU34_UB1_27: U34_UB1.27
NetU34_UB1_29: U34_UB1.29
NetU34_UB1_30: U34_UB1.30
NetU34_UB1_32: U34_UB1.32
NetU34_UB1_33: U34_UB1.33
NetU34_UB2_16: U34_UB2.16
NetU34_UB2_17: U34_UB2.17
NetU34_UB2_19: U34_UB2.19
NetU34_UB2_20: U34_UB2.20
NetU34_UB2_22: U34_UB2.22
NetU34_UB2_23: U34_UB2.23
NetU34_UB2_26: U34_UB2.26
NetU34_UB2_27: U34_UB2.27
NetU34_UB2_29: U34_UB2.29
NetU34_UB2_30: U34_UB2.30
NetU34_UB2_32: U34_UB2.32
NetU34_UB2_33: U34_UB2.33
NetU35_UB1_3: U35_UB1.3
NetU35_UB1_6: U35_UB1.6
NetU35_UB2_3: U35_UB2.3
NetU35_UB2_6: U35_UB2.6
NetU37_UB1_2: U37_UB1.2
NetU37_UB2_2: U37_UB2.2
NetU38_UB1_2: U38_UB1.2
NetU38_UB2_2: U38_UB2.2
NetU40_UB1_2: U40_UB1.2
NetU40_UB2_2: U40_UB2.2
NetU41_UB1_2: U41_UB1.2
NetU41_UB2_2: U41_UB2.2
NetU43_UB1_2: U43_UB1.2
NetU43_UB2_2: U43_UB2.2
NetU44_UB1_2: U44_UB1.2
NetU44_UB2_2: U44_UB2.2
NetU45_UB1_2: U45_UB1.2
NetU45_UB2_2: U45_UB2.2
NetU51_UB1_4: U51_UB1.4
NetU51_UB2_4: U51_UB2.4
NetU52_UB1_5: U52_UB1.5
NetU52_UB1_7: U52_UB1.7
NetU52_UB1_10: U52_UB1.10
NetU52_UB1_12: U52_UB1.12
NetU52_UB2_5: U52_UB2.5
NetU52_UB2_7: U52_UB2.7
NetU52_UB2_10: U52_UB2.10
NetU52_UB2_12: U52_UB2.12
NetU53_UB1_16: U53_UB1.16
NetU53_UB1_17: U53_UB1.17
NetU53_UB1_19: U53_UB1.19
NetU53_UB1_20: U53_UB1.20
NetU53_UB1_22: U53_UB1.22
NetU53_UB1_23: U53_UB1.23
NetU53_UB1_26: U53_UB1.26
NetU53_UB1_27: U53_UB1.27
NetU53_UB1_29: U53_UB1.29
NetU53_UB1_30: U53_UB1.30
NetU53_UB1_32: U53_UB1.32
NetU53_UB1_33: U53_UB1.33
NetU53_UB2_16: U53_UB2.16
NetU53_UB2_17: U53_UB2.17
NetU53_UB2_19: U53_UB2.19
NetU53_UB2_20: U53_UB2.20
NetU53_UB2_22: U53_UB2.22
NetU53_UB2_23: U53_UB2.23
NetU53_UB2_26: U53_UB2.26
NetU53_UB2_27: U53_UB2.27
NetU53_UB2_29: U53_UB2.29
NetU53_UB2_30: U53_UB2.30
NetU53_UB2_32: U53_UB2.32
NetU53_UB2_33: U53_UB2.33
NetU55_UB1_67: U55_UB1.67
NetU55_UB1_81: U55_UB1.81
NetU55_UB1_82: U55_UB1.82
NetU55_UB1_115: U55_UB1.115
NetU55_UB1_116: U55_UB1.116
NetU55_UB1_119: U55_UB1.119 | length 0.9
  Top Layer w0.254: 56.04,53.623 U55_UB1.119@56.04,54.491
NetU55_UB1_122: U55_UB1.122
NetU55_UB1_123: U55_UB1.123
NetU55_UB1_124: U55_UB1.124
NetU55_UB1_127: U55_UB1.127
NetU55_UB1_128: U55_UB1.128
NetU55_UB1_129: U55_UB1.129
NetU55_UB1_130: U55_UB1.130
NetU55_UB1_131: U55_UB1.131
NetU55_UB1_132: U55_UB1.132
NetU55_UB1_133: U55_UB1.133
NetU55_UB1_134: U55_UB1.134
NetU55_UB1_135: U55_UB1.135
NetU55_UB1_136: U55_UB1.136
NetU55_UB1_151: U55_UB1.151
NetU55_UB1_152: U55_UB1.152
NetU55_UB1_153: U55_UB1.153
NetU55_UB1_156: U55_UB1.156
NetU55_UB1_157: U55_UB1.157
NetU55_UB1_158: U55_UB1.158
NetU55_UB1_161: U55_UB1.161
NetU55_UB1_162: U55_UB1.162
NetU55_UB1_163: U55_UB1.163
NetU55_UB1_164: U55_UB1.164
NetU55_UB1_165: U55_UB1.165
NetU55_UB1_168: U55_UB1.168
NetU55_UB1_169: U55_UB1.169
NetU55_UB1_172: U55_UB1.172
NetU55_UB1_173: U55_UB1.173
NetU55_UB1_174: U55_UB1.174
NetU55_UB1_175: U55_UB1.175
NetU55_UB2_67: U55_UB2.67
NetU55_UB2_81: U55_UB2.81
NetU55_UB2_82: U55_UB2.82
NetU55_UB2_115: U55_UB2.115
NetU55_UB2_116: U55_UB2.116
NetU55_UB2_119: U55_UB2.119
NetU55_UB2_122: U55_UB2.122
NetU55_UB2_123: U55_UB2.123
NetU55_UB2_124: U55_UB2.124
NetU55_UB2_127: U55_UB2.127
NetU55_UB2_128: U55_UB2.128
NetU55_UB2_129: U55_UB2.129
NetU55_UB2_130: U55_UB2.130
NetU55_UB2_131: U55_UB2.131
NetU55_UB2_132: U55_UB2.132
NetU55_UB2_133: U55_UB2.133
NetU55_UB2_134: U55_UB2.134
NetU55_UB2_135: U55_UB2.135
NetU55_UB2_136: U55_UB2.136
NetU55_UB2_151: U55_UB2.151
NetU55_UB2_152: U55_UB2.152
NetU55_UB2_153: U55_UB2.153
NetU55_UB2_156: U55_UB2.156
NetU55_UB2_157: U55_UB2.157
NetU55_UB2_158: U55_UB2.158
NetU55_UB2_161: U55_UB2.161
NetU55_UB2_162: U55_UB2.162
NetU55_UB2_163: U55_UB2.163
NetU55_UB2_164: U55_UB2.164
NetU55_UB2_165: U55_UB2.165
NetU55_UB2_168: U55_UB2.168
NetU55_UB2_169: U55_UB2.169
NetU55_UB2_172: U55_UB2.172
NetU55_UB2_173: U55_UB2.173
NetU55_UB2_174: U55_UB2.174
NetU55_UB2_175: U55_UB2.175
NetU56_UB1_4: U56_UB1.4
NetU56_UB2_4: U56_UB2.4
NetU61_UB1_2: U61_UB1.2
NetU61_UB1_14: U61_UB1.14
NetU61_UB2_2: U61_UB2.2
NetU61_UB2_14: U61_UB2.14
NetU63_2: U63.2
NetU63_4: U63.4
NetU63_11: U63.11
NetU63_15: U63.15
NetU65_4: U65.4
NetU66_4: U66.4
NetU68_16: U68.16
NetU68_18: U68.18
NetU68_19: U68.19
NetU68_20: U68.20
NetU68_32: U68.32
NetU68_36: U68.36
NetU68_37: U68.37
NetU68_38: U68.38
NetU68_39: U68.39
NetU68_40: U68.40
NetU68_41: U68.41
NetU68_42: U68.42
NetU68_43: U68.43
NetUP1_3: UP1.3
NetUP4_UB1_4: UP4_UB1.4
NetUP4_UB1_6: UP4_UB1.6
NetUP4_UB2_4: UP4_UB2.4
NetUP4_UB2_6: UP4_UB2.6
NetUP6_UB1_4: UP6_UB1.4
NetUP6_UB2_4: UP6_UB2.4
OPEN_INT1_UB1: R352_UB1.2 U55_UB1.21 U58_UB1.22 | length 21.3
  Top Layer w0.254: U55_UB1.21@52.54,80.391 52.54,88.532 53.289,89.281 62.738,89.281 R352_UB1.2@63.017,89.56 ; U58_UB1.22@60.326,87.07 60.326,89.28
OPEN_INT1_UB2: R352_UB2.2 U55_UB2.21 U58_UB2.22 | length 19.8
  Top Layer w0.254: U55_UB2.21@209.385,80.696 209.385,79.667 210.083,78.969 v1(210.693,78.969) ; U58_UB2.22@214.419,88.34 214.419,87.18 215.218,86.382 v1(215.443,86.382) 216.277,86.382 217.068,87.173 R352_UB2.2@217.068,87.986
  Bottom Layer w0.254: v1(210.693,78.969) 210.693,80.264 209.956,81.001 209.956,84.16 211.547,85.75 214.808,85.75 215.439,86.382 v1(215.443,86.382)
PT1000_AN1: R343_UB1.1 U5.C4 | length 40
  Top Layer w0.254: v1(114.605,3.937) 114.579,3.962 114.579,4.724 117.932,8.077 117.932,35.154 R343_UB1.1@117.881,35.204
  Mid-Layer 1 w0.254: U5.C4@112.7,-2.627 113.741,-1.586 113.741,3.073 v1(114.605,3.937)
PT1000_AN1_UB2: R343_UB2.1 U5.E10 | length 49
  Top Layer w0.254: U5.E10@124.7,1.373 124.7,1.739 126.238,3.277 126.238,8.077 124.587,9.728 124.587,27.991 125.755,29.159 v1(125.755,29.573) ; v1(140.36,34.29) R343_UB2.1@140.36,35.281
  Mid-Layer 3 w0.381: v1@125.73,29.515 125.73,31.877 127.241,33.388 131.356,33.388 132.258,34.29 v1(140.36,34.29)
PT1000_AP1: R335_UB1.2 U5.B4 U57_UB1.12 | length 54.4
  Top Layer w0.254: v1@114.656,2.819 115.291,3.454 115.291,4.242 118.638,7.589 118.638,33.122 v1@119.431,33.914 ; v1@119.405,34.112 R335_UB1.2@119.405,35.204 ; v1(120.142,43.256) 120.65,43.764 U57_UB1.12@122.423,43.764
  Mid-Layer 2 w0.254: U5.B4@112.7,-4.627 113.716,-3.611 113.716,1.981 v1(114.605,2.87) ; v1@119.405,34.087 119.405,42.52 v1(120.142,43.256)
  other v1: 119.405,33.909
PT1000_AP1_UB2: R335_UB2.2 U5.D10 U57_UB2.12 | length 63.2
  Top Layer w0.254: U5.D10@124.7,-0.627 125.705,0.377 125.705,1.93 126.848,3.073 126.848,8.514 125.374,9.988 125.374,27.864 126.594,29.083 v1(126.594,29.903) ; v1(141.681,34.29) R335_UB2.2@141.681,35.281 ; v1(143.332,43.815) U57_UB2.12@144.704,43.815
  Mid-Layer 2 w0.254: v1(141.681,34.29) 141.681,42.164 v1(143.332,43.815)
  Mid-Layer 3 w0.381: v1(126.594,29.903) 126.594,31.852 127.121,32.379 127.121,32.442 127.178,32.442 127.541,32.804 131.632,32.804 132.407,33.579 141.021,33.579 141.681,34.239 v1(141.681,34.29)
PT1000_BCN1: R384.1 U5.E6 | length 96.7
  Top Layer w0.254: U5.E6@116.7,1.373 116.7,1.486 116.789,1.575 U5.E6@116.789,1.829
  Top Layer w0.381: U5.E6@116.7,1.486 116.7,2.476 117.577,3.353 118.72,3.353 v1(119.228,3.861)
  Top Layer w0.762: v1(124.308,80.289) 124.308,85.649 124.595,85.936 126.34,85.936 R384.1@126.34,86.97
  Mid-Layer 2 w0.381: v1(119.228,3.861) 119.99,4.623 119.99,28.448 122.707,31.166 122.707,31.775 124.384,33.452 124.384,34.468 126.086,36.17 126.086,37.084 128.93,39.929 128.93,44.069 129.997,45.136 129.997,51.918 126.619,55.296 126.111,55.296 124.308,57.099 v1(124.308,80.289)
PT1000_BCP1: R376.2 U5.D6 U64.12 | length 114.4
  Top Layer w0.254: U5.D6@116.7,-0.627 U5.D6@116.746,-0.627 ; U5.D6@116.873,-0.627 U5.D6@116.746,-0.627 ; v1(120.167,3.835) 119.024,2.692 118.085,2.692 117.704,2.311 117.704,0.33 U5.D6@116.746,-0.627
  Top Layer w0.381: U64.12@132.563,95.326 133.706,95.326 134.087,94.945 134.087,88.976 v2(133.858,88.748) 133.731,88.621 R376.2@132.817,88.621
  Mid-Layer 2 w0.381: v1(120.167,3.835) 120.853,4.521 120.853,28.042 123.495,30.683 123.495,31.039 125.12,32.664 125.12,34.036 126.822,35.738 126.822,36.855 129.616,39.649 129.616,43.231 130.759,44.374 130.759,52.21 125.082,57.887 125.082,75.755 125.146,75.819 ; v1(125.146,75.006) 125.146,75.819 ; v2(133.858,88.748) 133.858,82.144 131.42,79.705 126.873,79.705 125.146,77.978 125.146,75.819
PWM1_UB1: U55_UB1.5 U58_UB1.21 | length 7
  Top Layer w0.254: U58_UB1.21@59.676,87.07 59.676,84.723 60.54,83.859 U55_UB1.5@60.54,80.391
PWM1_UB2: U55_UB2.5 U58_UB2.21 | length 9.1
  Top Layer w0.254: U58_UB2.21@213.769,88.34 213.769,87.17 217.385,83.554 U55_UB2.5@217.385,80.696
PWM2_UB1: U55_UB1.6 U58_UB1.20 | length 7.1
  Top Layer w0.254: U58_UB1.20@59.026,87.07 59.026,84.332 60.04,83.317 U55_UB1.6@60.04,80.391
PWM2_UB2: U55_UB2.6 U58_UB2.20 | length 9.2
  Top Layer w0.254: U58_UB2.20@213.119,88.34 213.119,86.956 216.885,83.19 U55_UB2.6@216.885,80.696
PWM3_UB1: U55_UB1.7 U58_UB1.19 | length 7.2
  Top Layer w0.254: U58_UB1.19@58.376,87.07 58.376,84.118 59.54,82.954 U55_UB1.7@59.54,80.391
PWM3_UB2: U55_UB2.7 U58_UB2.19 | length 9.3
  Top Layer w0.254: U58_UB2.19@212.469,88.34 212.469,86.895 216.385,82.979 U55_UB2.7@216.385,80.696
PWM4_UB1: U55_UB1.10 U58_UB1.18 | length 6.8
  Top Layer w0.254: U58_UB1.18@57.726,87.07 57.726,83.701 58.04,83.387 U55_UB1.10@58.04,80.391
PWM4_UB2: U55_UB2.10 U58_UB2.18 | length 8.9
  Top Layer w0.254: U58_UB2.18@211.819,88.34 211.819,86.834 214.885,83.768 U55_UB2.10@214.885,80.696
PWM5_UB1: U55_UB1.11 U58_UB1.17 | length 6.9
  Top Layer w0.254: U58_UB1.17@57.076,87.07 57.076,83.513 57.54,83.049 U55_UB1.11@57.54,80.391
PWM5_UB2: U55_UB2.11 U58_UB2.17 | length 9
  Top Layer w0.254: U58_UB2.17@211.169,88.34 211.169,86.696 214.385,83.481 U55_UB2.11@214.385,80.696
PWM6_UB1: U55_UB1.12 U58_UB1.16 | length 6.9
  Top Layer w0.254: U58_UB1.16@56.426,87.07 56.426,83.325 57.04,82.711 U55_UB1.12@57.04,80.391
PWM6_UB2: U55_UB2.12 U58_UB2.16 | length 9
  Top Layer w0.254: U58_UB2.16@210.519,88.34 210.519,86.596 213.885,83.23 U55_UB2.12@213.885,80.696
R/#W_UB1: R322_UB1.2
R/#W_UB2: R322_UB2.2
RDC_A0_UB1: U34_UB1.44 U53_UB1.44 U55_UB1.65 | length 60.1
  Top Layer w0.254: U55_UB1.65@38.84,68.191 41.064,68.191 44.755,71.882 60.528,71.882 61.214,71.196 v1(61.214,71.12) ; v1(67.361,70.841) 67.945,70.841 68.218,71.113 U53_UB1.44@70.18,71.113 71.762,71.113 72.644,70.231 72.644,53.848 75.191,51.301 U34_UB1.44@79.019,51.301
  Mid-Layer 2 w0.254: v1(61.214,71.12) 67.081,71.12 v1(67.361,70.841)
RDC_A0_UB2: U34_UB2.44 U53_UB2.44 U55_UB2.65 | length 45.2
  Top Layer w0.254: U53_UB2.44@180.365,80.118 183.762,80.118 186.03,77.851 186.03,59.233 186.226,59.036 U34_UB2.44@188.798,59.036 190.227,59.036 190.525,59.334 190.525,61.57 189.23,62.865 189.23,67.031 190.221,68.021 193.269,68.021 193.743,68.496 U55_UB2.65@195.685,68.496
RDC_A1_UB1: U34_UB1.43 U53_UB1.43 U55_UB1.66 | length 59.7
  Top Layer w0.254: U55_UB1.66@38.84,67.691 41.427,67.691 45.085,71.349 60.147,71.349 v1@60.363,71.133 ; v1(67.615,71.704) 67.706,71.613 U53_UB1.43@70.18,71.613 72.024,71.613 73.127,70.51 73.127,54.407 75.732,51.801 U34_UB1.43@79.019,51.801
  Mid-Layer 2 w0.254: v1@60.363,71.133 60.935,71.704 v1(67.615,71.704)
  other v1: 60.376,71.12
RDC_A1_UB2: U34_UB2.43 U53_UB2.43 U55_UB2.66 | length 45.2
  Top Layer w0.254: U53_UB2.43@180.365,79.618 183.45,79.618 185.522,77.546 185.522,58.877 185.863,58.536 U34_UB2.43@188.798,58.536 190.59,58.536 191.033,58.979 191.033,61.9 189.738,63.195 189.738,66.65 190.627,67.539 193.675,67.539 194.132,67.996 U55_UB2.66@195.685,67.996
RDC_FSYNC_UB1: U34_UB1.40 U53_UB1.40 U55_UB1.99 | length 65.1
  Top Layer w0.254: U55_UB1.99@46.04,54.491 46.04,61.28 50.622,65.862 59.741,65.862 61.265,67.386 61.265,70.129 61.849,70.714 v1(61.849,72.288) ; v1(67.564,72.568) 67.564,72.631 68.047,73.113 U53_UB1.40@70.18,73.113 72.175,73.113 73.66,71.628 73.66,55.22 75.578,53.301 U34_UB1.40@79.019,53.301
  Mid-Layer 2 w0.254: v1(61.849,72.288) 67.222,72.288 67.564,72.631 v1(67.564,72.568)
RDC_FSYNC_UB2: U34_UB2.40 U53_UB2.40 U55_UB2.99 | length 46
  Top Layer w0.254: U53_UB2.40@180.365,78.118 183.502,78.118 184.963,76.657 184.963,58.395 186.106,57.252 187.16,57.252 187.376,57.036 U34_UB2.40@188.798,57.036 190.802,57.036 v1@191.501,56.337 ; U55_UB2.99@202.885,54.796 202.885,53.198 v1(202.971,53.111)
  Mid-Layer 2 w0.254: v1(191.465,56.337) 195.428,52.375 200.228,52.375 200.965,53.111 v1(202.971,53.111)
RDC_RES0_UB1: U34_UB1.47 U53_UB1.47 U55_UB1.90 | length 63.5
  Top Layer w0.254: U55_UB1.90@41.54,54.491 41.54,52.262 v1(42.012,51.791) ; v1(64.973,48.641) 71.755,48.641 v1(72.238,49.124) ; U53_UB1.47@70.18,69.613 71.484,69.613 71.653,69.444 71.653,52.07 73.922,49.801 U34_UB1.47@79.019,49.801
  Mid-Layer 2 w0.254: v1(42.012,51.791) 42.443,51.359 57.175,51.359 59.893,48.641 v1(64.973,48.641) ; v1@72.212,49.149 v1(73.381,50.317)
RDC_RES0_UB2: U34_UB2.47 U53_UB2.47 U55_UB2.90 | length 43
  Top Layer w0.254: U53_UB2.47@180.365,81.618 184.345,81.618 187.046,78.918 187.046,61.036 187.546,60.536 U34_UB2.47@188.798,60.536 ; v1(195.072,55.296) 196.545,55.296 196.799,55.55 196.825,55.55 197.358,56.083 198.095,56.083 198.385,55.793 U55_UB2.90@198.385,54.796
  Mid-Layer 2 w0.254: v1(187.198,60.935) 190.144,60.935 194.564,56.515 194.564,55.804 v1(195.072,55.296)
RDC_RES1_UB1: U34_UB1.46 U53_UB1.46 U55_UB1.91 | length 62.2
  Top Layer w0.254: 42.04,53.111 42.04,53.007 ; U55_UB1.91@42.04,54.491 42.04,53.007 ; v1(42.494,52.553) 42.04,53.007 ; v1(64.745,49.378) 67.132,49.378 70.383,49.378 v1(70.409,49.403) ; U53_UB1.46@70.18,70.113 71.873,70.113 72.187,69.799 72.187,52.883 74.768,50.301 U34_UB1.46@78.054,50.301 U34_UB1.46@79.019,50.301
  Mid-Layer 2 w0.254: v1(42.494,52.553) 42.951,52.095 57.683,52.095 60.401,49.378 v1(64.745,49.378) ; v1(70.409,49.403) 70.409,49.352 v1(73.025,51.968)
RDC_RES1_UB2: U34_UB2.46 U53_UB2.46 U55_UB2.91 | length 43.1
  Top Layer w0.254: U53_UB2.46@180.365,81.118 183.88,81.118 186.588,78.41 186.588,60.718 187.227,60.079 188.755,60.079 U34_UB2.46@188.798,60.036 ; v1(193.777,56.083) 193.802,56.109 196.469,56.109 196.901,56.54 198.298,56.54 198.885,55.953 U55_UB2.91@198.885,54.796
  Mid-Layer 2 w0.254: v1(186.715,60.401) 186.905,60.401 187.21,60.096 189.808,60.096 193.777,56.127 v1(193.777,56.083)
RDC_RESET_UB1: U34_UB1.35 U53_UB1.35 U55_UB1.88 | length 74.6
  Top Layer w0.254: U55_UB1.88@38.84,56.691 40.74,56.691 42.367,58.318 42.367,63.779 46.025,67.437 v1@60.223,67.437 ; U53_UB1.35@70.18,75.613 72.951,75.613 75.819,72.746 75.819,56.82 76.837,55.801 U34_UB1.35@79.019,55.801
  Mid-Layer 2 w0.254: v1@60.528,67.437 71.704,67.437 74.155,69.888 v1@74.155,74.447
  other v1: 60.376,67.437 74.219,74.447
RDC_RESET_UB2: U34_UB2.35 U53_UB2.35 U55_UB2.88 | length 35.5
  Top Layer w0.254: U53_UB2.35@180.365,75.618 181.912,75.618 182.905,74.625 182.905,56.744 185.113,54.536 U34_UB2.35@188.798,54.536 191.112,54.536 193.572,56.996 U55_UB2.88@195.685,56.996
RDC_SAMPLE_UB1: U34_UB1.36 U53_UB1.36 U55_UB1.111 | length 54.8
  Top Layer w0.254: U55_UB1.111@52.04,54.491 52.04,52.557 53.721,50.876 70.256,50.876 70.993,51.613 v1(70.993,51.714) ; U53_UB1.36@70.18,75.113 72.588,75.113 75.286,72.415 75.286,56.109 76.093,55.301 U34_UB1.36@79.019,55.301
  Mid-Layer 2 w0.254: v1@70.968,51.638 v1(75.387,56.058)
RDC_SAMPLE_UB2: U34_UB2.36 U53_UB2.36 U55_UB2.111 | length 57.1
  Top Layer w0.254: U53_UB2.36@180.365,76.118 182.276,76.118 183.413,74.981 183.413,57.353 v1(185.382,55.385) 185.73,55.036 U34_UB2.36@188.798,55.036 ; v1(208.255,53.061) 208.458,53.061 208.885,53.488 U55_UB2.111@208.885,54.796
  Mid-Layer 2 w0.254: v1(185.382,55.385) 185.382,53.81 187.3,51.892 200.965,51.892 201.6,52.527 ; 203.175,52.527 201.6,52.527 ; v1(208.255,53.061) 208.077,53.238 204.648,53.238 203.937,52.527 201.6,52.527
RDC_SCLK_UB1: R350_UB1.2 U34_UB1.37 U53_UB1.37 | length 43.6
  Top Layer w0.254: v1(58.75,74.168) 60.757,74.168 v1(61.189,74.6) ; v1@67.564,74.6 67.779,74.6 67.793,74.613 U53_UB1.37@70.18,74.613 72.249,74.613 74.727,72.136 74.727,55.804 75.729,54.801 U34_UB1.37@79.019,54.801
  Mid-Layer 2 w0.254: v1(61.189,74.6) 61.214,74.574 62.992,74.574 63.17,74.752 67.412,74.752 v1@67.564,74.6
  Bottom Layer w0.254: R350_UB1.2@54.889,71.628 54.889,72.136 56.921,74.168 v1(58.75,74.168)
  other v1: 67.564,74.701
RDC_SCLK_UB2: R350_UB2.2 U34_UB2.37 U53_UB2.37 | length 37
  Top Layer w0.254: U53_UB2.37@180.365,76.618 182.767,76.618 183.921,75.463 183.921,57.81 186.196,55.536 U34_UB2.37@188.798,55.536 v1@190.551,55.536 ; v1(191.008,49.536) 191.014,49.53 R350_UB2.2@191.973,49.53
  Bottom Layer w0.254: v1(190.602,55.524) 190.703,55.423 190.703,54 190.602,54 190.119,53.518 190.119,50.241 190.824,49.536 v1(191.008,49.536)
RDC_SDI_UB1: R349_UB1.2 U34_UB1.38 U53_UB1.38 | length 45.2
  Top Layer w0.254: v1(66.687,73.99) 66.81,74.113 U53_UB1.38@70.18,74.113 71.962,74.113 74.193,71.882 74.193,55.575 75.467,54.301 U34_UB1.38@79.019,54.301
  Mid-Layer 2 w0.254: v1(61.417,73.076) 65.773,73.076 v1(66.687,73.99)
  Bottom Layer w0.254: R349_UB1.2@53.416,73.152 55.067,74.803 59.69,74.803 v1(61.417,73.076)
RDC_SDI_UB2: R349_UB2.2 U34_UB2.38 U53_UB2.38 | length 41.6
  Top Layer w0.254: U53_UB2.38@180.365,77.118 183.105,77.118 184.455,75.768 184.455,58.147 186.566,56.036 U34_UB2.38@188.798,56.036 ; v1(191.033,47.015) 191.364,46.685 R349_UB2.2@191.973,46.685
  Bottom Layer w0.254: v1(186.03,56.591) 186.03,49.632 187.858,47.803 190.246,47.803 v1(191.033,47.015)
RDC_SDO_UB1: R348_UB1.2 U52_UB1.4 U52_UB1.6 | length 30.2
  Top Layer w0.254: v1@76.81,64.059 76.862,64.111 U52_UB1.6@78.74,64.111 80.316,64.111 80.569,64.364 80.569,65.227 80.385,65.411 U52_UB1.4@78.74,65.411
  Mid-Layer 2 w0.254: v1(61.9,61.849) 63.703,61.849 65.938,59.614 68.719,59.614 73.164,64.059 v1(76.835,64.059)
  Bottom Layer w0.254: R348_UB1.2@56.4,62.738 61.011,62.738 v1(61.9,61.849)
RDC_SDO_UB2: R348_UB2.2 U52_UB2.4 U52_UB2.6 | length 28
  Top Layer w0.254: U52_UB2.4@180.848,65.806 179.482,65.806 179.273,66.015 v1(179.273,66.98) 179.399,67.106 U52_UB2.6@180.848,67.106 ; v1(190.932,52.654) 190.906,52.629 191.786,52.629 R348_UB2.2@191.989,52.426
  Mid-Layer 2 w0.254: v1(179.299,63.094) 179.299,60.071 183.032,56.337 185.293,56.337 186.309,55.321 186.309,53.924 187.579,52.654 v1(190.932,52.654)
  Bottom Layer w0.254: v1(179.273,66.98) 179.426,66.827 179.426,63.221 v1(179.299,63.094)
RS422_+5V_UB1: C420_UB1.1 C421_UB1.1 C422_UB1.1 LED14_UB1.1 U62_UB1.12 U62_UB1.19 | length 25.7
  Top Layer w0.508: 109.093,20.091 109.118,20.117
  Top Layer w0.762: v2@103.251,20.447 103.251,20.345 103.48,20.117 U62_UB1.12@105.212,20.117 109.118,20.117 110.414,20.117 C420_UB1.1@111.15,20.853 ; v2@103.429,28.989 103.436,28.981 U62_UB1.19@105.212,28.981 ; U62_UB1.19@105.238,28.956 LED14_UB1.1@107.62,28.956 ; C421_UB1.1@109.093,17.221 109.093,20.091
  Mid-Layer 2 w0.762: v2(103.276,20.472) 102.819,20.472 102.21,21.082 102.21,28.6 102.616,29.007 v2(103.403,29.007)
RS422_+5V_UB2: C420_UB2.1 C421_UB2.1 C422_UB2.1 LED14_UB2.1 U62_UB2.12 U62_UB2.19 | length 30.4
  Top Layer w0.762: C420_UB2.1@144.729,26.975 144.729,27.915 v2@144.751,27.936 ; v2(144.755,27.94) v2@144.751,27.936 ; C422_UB2.1@146.914,26.492 C421_UB2.1@146.914,27.936 v2@144.751,27.936 ; LED14_UB2.1@148.655,19.558 148.883,19.787 U62_UB2.19@151.455,19.787 v2(153.213,19.787) ; U62_UB2.12@151.455,28.651 v2(153.035,28.651)
  Mid-Layer 2 w1.27: v2(144.755,27.94) 146.583,27.94 148.031,26.492 151.257,26.492 151.282,26.467 ; v2(153.035,28.651) 151.384,28.651 151.257,28.524 151.282,28.499 151.282,26.467 ; v2(153.213,19.787) 151.359,19.787 151.282,19.863 151.282,26.467
RS422_A_UB2: R366_UB2.2 R421.2 U62_UB2.18 | length 8.4
  Top Layer w0.381: v1(144.272,21.285) 144.424,21.285 144.602,21.107 R366_UB2.2@148.579,21.107 148.629,21.057 U62_UB2.18@151.455,21.057
  Bottom Layer w0.381: R421.2@143.18,21.285 v1(144.272,21.285)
